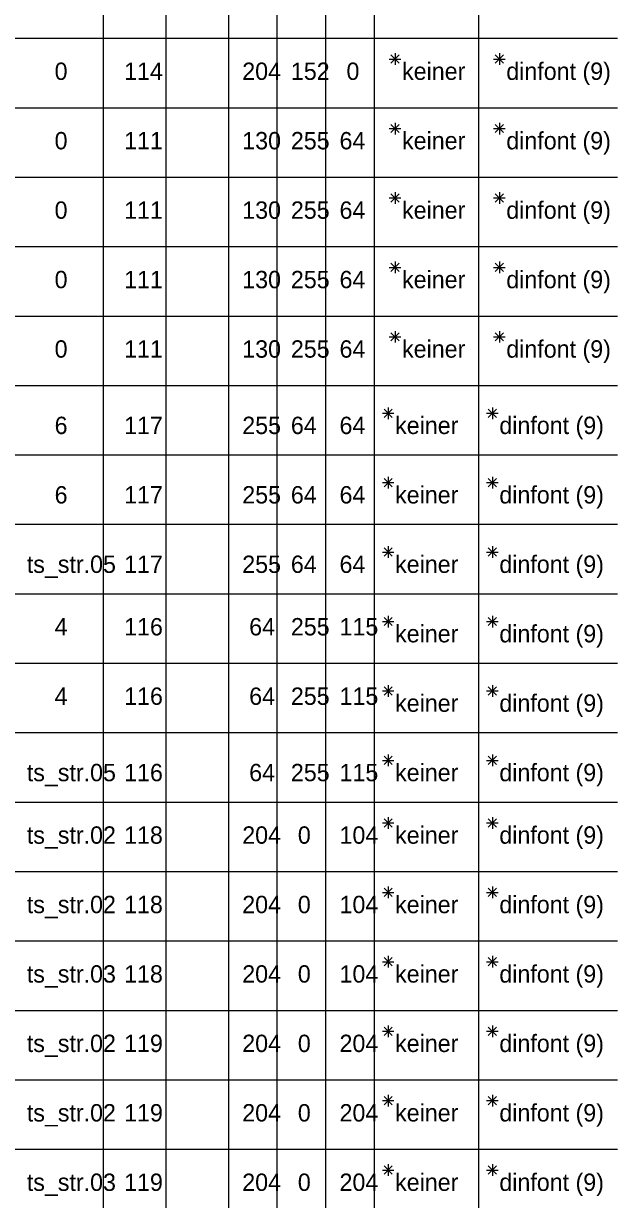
# Model space of a CAD drawing. Extents: x -14.5 to 23.8, y -56.3 to 8.
# Drawn here: x 11.73 to 15.97, y -15.36 to -6.89 of the extents above; entities that cross this region are included whole.
import ezdxf

# ---------------------------------------------------------------- set-up
doc = ezdxf.new("R2010")
doc.units = 0
doc.layers.add('Default', color=7, linetype='Continuous')

msp = doc.modelspace()

# ---------------------------------------------------------------- linework, layer by layer
at = {"layer": 'Default'}
for p, q in [((12.3, -0.35), (12.3, -44.5)), ((12.75, -0.35), (12.75, -44.5)), ((13.2, -0.35), (13.2, -44.5)), ((14.25, -0.35), (14.25, -48)), ((15, -0.35), (15, -48)), ((13.55, -0.75), (13.55, -44.5)), ((13.9, -0.75), (13.9, -44.5)), ((0, -7), (16, -7)), ((14.4, -7.1081), (14.4, -7.1919)), ((15.15, -7.1081), (15.15, -7.1919)), ((14.3581, -7.15), (14.4419, -7.15)), ((14.3703, -7.1203), (14.4297, -7.1797)), ((14.4297, -7.1203), (14.3703, -7.1797)), ((15.1081, -7.15), (15.1919, -7.15)), ((15.1203, -7.1203), (15.1797, -7.1797)), ((15.1797, -7.1203), (15.1203, -7.1797)), ((0, -7.5), (16, -7.5)), ((14.3703, -7.6203), (14.4297, -7.6797)), ((14.4297, -7.6203), (14.3703, -7.6797)), ((14.4, -7.6081), (14.4, -7.6919)), ((15.1203, -7.6203), (15.1797, -7.6797)), ((15.1797, -7.6203), (15.1203, -7.6797)), ((15.15, -7.6081), (15.15, -7.6919)), ((14.3581, -7.65), (14.4419, -7.65)), ((15.1081, -7.65), (15.1919, -7.65)), ((0, -8), (16, -8)), ((14.3703, -8.1203), (14.4297, -8.1797)), ((14.4297, -8.1203), (14.3703, -8.1797)), ((14.4, -8.1081), (14.4, -8.1919)), ((15.1203, -8.1203), (15.1797, -8.1797)), ((15.1797, -8.1203), (15.1203, -8.1797)), ((15.15, -8.1081), (15.15, -8.1919)), ((14.3581, -8.15), (14.4419, -8.15)), ((15.1081, -8.15), (15.1919, -8.15)), ((0, -8.5), (16, -8.5)), ((14.3703, -8.6203), (14.4297, -8.6797)), ((14.4297, -8.6203), (14.3703, -8.6797)), ((14.4, -8.6081), (14.4, -8.6919)), ((15.1203, -8.6203), (15.1797, -8.6797)), ((15.1797, -8.6203), (15.1203, -8.6797)), ((15.15, -8.6081), (15.15, -8.6919)), ((14.3581, -8.65), (14.4419, -8.65)), ((15.1081, -8.65), (15.1919, -8.65)), ((0, -9), (16, -9)), ((14.3703, -9.1203), (14.4297, -9.1797)), ((14.4297, -9.1203), (14.3703, -9.1797)), ((14.4, -9.1081), (14.4, -9.1919)), ((15.1203, -9.1203), (15.1797, -9.1797)), ((15.1797, -9.1203), (15.1203, -9.1797)), ((15.15, -9.1081), (15.15, -9.1919)), ((14.3581, -9.15), (14.4419, -9.15)), ((15.1081, -9.15), (15.1919, -9.15)), ((0, -9.5), (16, -9.5)), ((14.3081, -9.7), (14.3919, -9.7)), ((14.3203, -9.6703), (14.3797, -9.7297)), ((14.3797, -9.6703), (14.3203, -9.7297)), ((14.35, -9.6581), (14.35, -9.7419)), ((15.0581, -9.7), (15.1419, -9.7)), ((15.0703, -9.6703), (15.1297, -9.7297)), ((15.1297, -9.6703), (15.0703, -9.7297)), ((15.1, -9.6581), (15.1, -9.7419)), ((0, -10), (16, -10)), ((14.35, -10.1581), (14.35, -10.2419)), ((15.1, -10.1581), (15.1, -10.2419)), ((14.3081, -10.2), (14.3919, -10.2)), ((14.3203, -10.1703), (14.3797, -10.2297)), ((14.3797, -10.1703), (14.3203, -10.2297)), ((15.0581, -10.2), (15.1419, -10.2)), ((15.0703, -10.1703), (15.1297, -10.2297)), ((15.1297, -10.1703), (15.0703, -10.2297)), ((0, -10.5), (16, -10.5)), ((14.35, -10.6581), (14.35, -10.7419)), ((15.1, -10.6581), (15.1, -10.7419)), ((14.3081, -10.7), (14.3919, -10.7)), ((14.3203, -10.6703), (14.3797, -10.7297)), ((14.3797, -10.6703), (14.3203, -10.7297)), ((15.0581, -10.7), (15.1419, -10.7)), ((15.0703, -10.6703), (15.1297, -10.7297)), ((15.1297, -10.6703), (15.0703, -10.7297)), ((0, -11), (16, -11)), ((14.3203, -11.1703), (14.3797, -11.2297)), ((14.3797, -11.1703), (14.3203, -11.2297)), ((14.35, -11.1581), (14.35, -11.2419)), ((15.0703, -11.1703), (15.1297, -11.2297)), ((15.1297, -11.1703), (15.0703, -11.2297)), ((15.1, -11.1581), (15.1, -11.2419)), ((14.3081, -11.2), (14.3919, -11.2)), ((15.0581, -11.2), (15.1419, -11.2)), ((0, -11.5), (16, -11.5)), ((14.3203, -11.6703), (14.3797, -11.7297)), ((14.3797, -11.6703), (14.3203, -11.7297)), ((14.35, -11.6581), (14.35, -11.7419)), ((15.0703, -11.6703), (15.1297, -11.7297)), ((15.1297, -11.6703), (15.0703, -11.7297)), ((15.1, -11.6581), (15.1, -11.7419)), ((14.3081, -11.7), (14.3919, -11.7)), ((15.0581, -11.7), (15.1419, -11.7)), ((0, -12), (16, -12)), ((14.3203, -12.1703), (14.3797, -12.2297)), ((14.3797, -12.1703), (14.3203, -12.2297)), ((14.35, -12.1581), (14.35, -12.2419)), ((15.0703, -12.1703), (15.1297, -12.2297)), ((15.1297, -12.1703), (15.0703, -12.2297)), ((15.1, -12.1581), (15.1, -12.2419)), ((14.3081, -12.2), (14.3919, -12.2)), ((15.0581, -12.2), (15.1419, -12.2)), ((0, -12.5), (16, -12.5)), ((14.35, -12.6081), (14.35, -12.6919)), ((15.1, -12.6081), (15.1, -12.6919)), ((14.3081, -12.65), (14.3919, -12.65)), ((14.3203, -12.6203), (14.3797, -12.6797)), ((14.3797, -12.6203), (14.3203, -12.6797)), ((15.0581, -12.65), (15.1419, -12.65)), ((15.0703, -12.6203), (15.1297, -12.6797)), ((15.1297, -12.6203), (15.0703, -12.6797)), ((0, -13), (16, -13)), ((14.3203, -13.1203), (14.3797, -13.1797)), ((14.3797, -13.1203), (14.3203, -13.1797)), ((14.35, -13.1081), (14.35, -13.1919)), ((15.0703, -13.1203), (15.1297, -13.1797)), ((15.1297, -13.1203), (15.0703, -13.1797)), ((15.1, -13.1081), (15.1, -13.1919)), ((14.3081, -13.15), (14.3919, -13.15)), ((15.0581, -13.15), (15.1419, -13.15)), ((0, -13.5), (16, -13.5)), ((14.3203, -13.6203), (14.3797, -13.6797)), ((14.3797, -13.6203), (14.3203, -13.6797)), ((14.35, -13.6081), (14.35, -13.6919)), ((15.0703, -13.6203), (15.1297, -13.6797)), ((15.1297, -13.6203), (15.0703, -13.6797)), ((15.1, -13.6081), (15.1, -13.6919)), ((14.3081, -13.65), (14.3919, -13.65)), ((15.0581, -13.65), (15.1419, -13.65)), ((0, -14), (16, -14)), ((14.3203, -14.1203), (14.3797, -14.1797)), ((14.3797, -14.1203), (14.3203, -14.1797)), ((14.35, -14.1081), (14.35, -14.1919)), ((15.0703, -14.1203), (15.1297, -14.1797)), ((15.1297, -14.1203), (15.0703, -14.1797)), ((15.1, -14.1081), (15.1, -14.1919)), ((14.3081, -14.15), (14.3919, -14.15)), ((15.0581, -14.15), (15.1419, -14.15)), ((0, -14.5), (16, -14.5)), ((14.3203, -14.6203), (14.3797, -14.6797)), ((14.3797, -14.6203), (14.3203, -14.6797)), ((14.35, -14.6081), (14.35, -14.6919)), ((15.0703, -14.6203), (15.1297, -14.6797)), ((15.1297, -14.6203), (15.0703, -14.6797)), ((15.1, -14.6081), (15.1, -14.6919)), ((14.3081, -14.65), (14.3919, -14.65)), ((15.0581, -14.65), (15.1419, -14.65)), ((0, -15), (16, -15)), ((14.3081, -15.15), (14.3919, -15.15)), ((14.3203, -15.1203), (14.3797, -15.1797)), ((14.3797, -15.1203), (14.3203, -15.1797)), ((14.35, -15.1081), (14.35, -15.1919)), ((15.0581, -15.15), (15.1419, -15.15)), ((15.0703, -15.1203), (15.1297, -15.1797)), ((15.1297, -15.1203), (15.0703, -15.1797)), ((15.1, -15.1081), (15.1, -15.1919))]:
    msp.add_line(p, q, dxfattribs=at)

# ---------------------------------------------------------------- texts
for s, p in [('0', (11.95, -7.3)), ('114', (12.45, -7.3)), ('204', (13.3, -7.3)), ('152', (13.65, -7.3)), ('0', (14.05, -7.3)), ('keiner', (14.45, -7.3)), ('dinfont (9)', (15.2, -7.3)), ('0', (11.95, -7.8)), ('111', (12.45, -7.8)), ('130', (13.3, -7.8)), ('255', (13.65, -7.8)), ('64', (14, -7.8)), ('keiner', (14.45, -7.8)), ('dinfont (9)', (15.2, -7.8)), ('0', (11.95, -8.3)), ('111', (12.45, -8.3)), ('130', (13.3, -8.3)), ('255', (13.65, -8.3)), ('64', (14, -8.3)), ('keiner', (14.45, -8.3)), ('dinfont (9)', (15.2, -8.3)), ('0', (11.95, -8.8)), ('111', (12.45, -8.8)), ('130', (13.3, -8.8)), ('255', (13.65, -8.8)), ('64', (14, -8.8)), ('keiner', (14.45, -8.8)), ('dinfont (9)', (15.2, -8.8)), ('0', (11.95, -9.3)), ('111', (12.45, -9.3)), ('130', (13.3, -9.3)), ('255', (13.65, -9.3)), ('64', (14, -9.3)), ('keiner', (14.45, -9.3)), ('dinfont (9)', (15.2, -9.3)), ('6', (11.95, -9.85)), ('117', (12.45, -9.85)), ('255', (13.3, -9.85)), ('64', (13.65, -9.85)), ('64', (14, -9.85)), ('keiner', (14.4, -9.85)), ('dinfont (9)', (15.15, -9.85)), ('6', (11.95, -10.35)), ('117', (12.45, -10.35)), ('255', (13.3, -10.35)), ('64', (13.65, -10.35)), ('64', (14, -10.35)), ('keiner', (14.4, -10.35)), ('dinfont (9)', (15.15, -10.35)), ('ts_str.05', (11.75, -10.85)), ('117', (12.45, -10.85)), ('255', (13.3, -10.85)), ('64', (13.65, -10.85)), ('64', (14, -10.85)), ('keiner', (14.4, -10.85)), ('dinfont (9)', (15.15, -10.85)), ('4', (11.95, -11.3)), ('116', (12.45, -11.3)), ('64', (13.35, -11.3)), ('255', (13.65, -11.3)), ('115', (14, -11.3)), ('keiner', (14.4, -11.35)), ('dinfont (9)', (15.15, -11.35)), ('4', (11.95, -11.8)), ('116', (12.45, -11.8)), ('64', (13.35, -11.8)), ('255', (13.65, -11.8)), ('115', (14, -11.8)), ('keiner', (14.4, -11.85)), ('dinfont (9)', (15.15, -11.85)), ('ts_str.05', (11.75, -12.35)), ('116', (12.45, -12.35)), ('64', (13.35, -12.35)), ('255', (13.65, -12.35)), ('115', (14, -12.35)), ('keiner', (14.4, -12.35)), ('dinfont (9)', (15.15, -12.35)), ('ts_str.02', (11.75, -12.8)), ('118', (12.45, -12.8)), ('204', (13.3, -12.8)), ('0', (13.7, -12.8)), ('104', (14, -12.8)), ('keiner', (14.4, -12.8)), ('dinfont (9)', (15.15, -12.8)), ('ts_str.02', (11.75, -13.3)), ('118', (12.45, -13.3)), ('204', (13.3, -13.3)), ('0', (13.7, -13.3)), ('104', (14, -13.3)), ('keiner', (14.4, -13.3)), ('dinfont (9)', (15.15, -13.3)), ('ts_str.03', (11.75, -13.8)), ('118', (12.45, -13.8)), ('204', (13.3, -13.8)), ('0', (13.7, -13.8)), ('104', (14, -13.8)), ('keiner', (14.4, -13.8)), ('dinfont (9)', (15.15, -13.8)), ('ts_str.02', (11.75, -14.3)), ('119', (12.45, -14.3)), ('204', (13.3, -14.3)), ('0', (13.7, -14.3)), ('204', (14, -14.3)), ('keiner', (14.4, -14.3)), ('dinfont (9)', (15.15, -14.3)), ('ts_str.02', (11.75, -14.8)), ('119', (12.45, -14.8)), ('204', (13.3, -14.8)), ('0', (13.7, -14.8)), ('204', (14, -14.8)), ('keiner', (14.4, -14.8)), ('dinfont (9)', (15.15, -14.8)), ('ts_str.03', (11.75, -15.3)), ('119', (12.45, -15.3)), ('204', (13.3, -15.3)), ('0', (13.7, -15.3)), ('204', (14, -15.3)), ('keiner', (14.4, -15.3)), ('dinfont (9)', (15.15, -15.3))]:
    msp.add_text(s, height=0.125, dxfattribs=at).set_placement(p)

doc.saveas('drawing.dxf')
